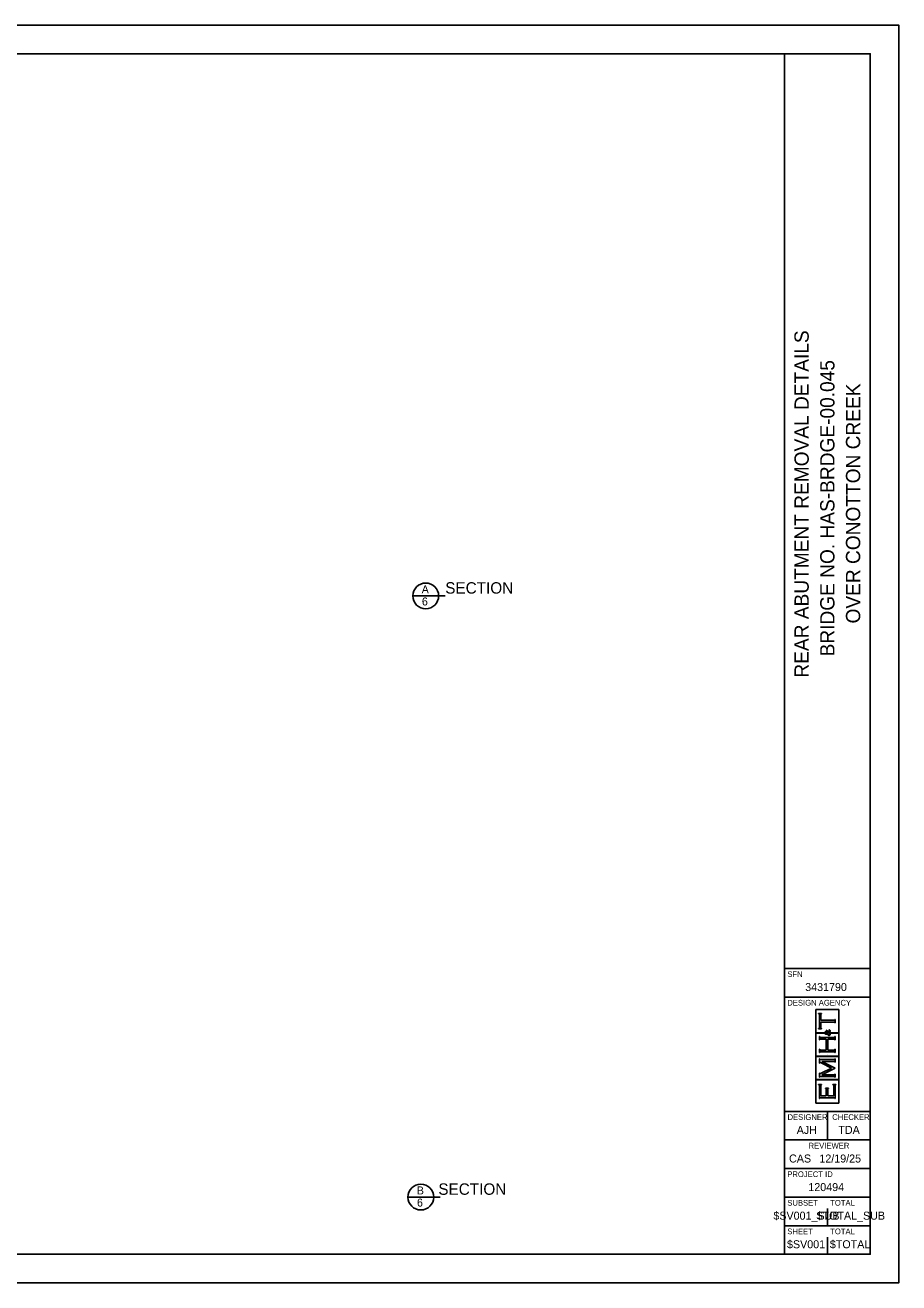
# Model space of a CAD drawing. Extents: x 0 to 34, y 0 to 22.
# Drawn here: x 18.73 to 34, y 0 to 22 of the extents above; entities that cross this region are included whole.
import ezdxf

# ---------------------------------------------------------------- set-up
doc = ezdxf.new("R2010")
doc.units = 0
for name, color, linetype in [('BR_P_Gen_Text', 7, 'Continuous'), ('SH_Border', 7, 'Continuous'), ('SH_Cut_Line', 7, 'Continuous'), ('SH_Data', 7, 'Continuous'), ('SH_Text', 7, 'Continuous')]:
    doc.layers.add(name, color=color, linetype=linetype)

msp = doc.modelspace()

# ---------------------------------------------------------------- linework, layer by layer
at = {"layer": 'SH_Border'}
for p, q in [((32, 0.5), (32, 21.5)), ((32, 5.5), (33.5, 5.5)), ((32, 5), (33.5, 5)), ((32, 3), (33.5, 3)), ((32.75, 3), (32.75, 2.5)), ((32, 2.5), (33.5, 2.5)), ((32, 2), (33.5, 2)), ((32, 1.5), (33.5, 1.5)), ((32, 1), (33.5, 1))]:
    msp.add_line(p, q, dxfattribs=at)
msp.add_lwpolyline([(1.5, 21.5), (33.5, 21.5), (33.5, 0.5), (1.5, 0.5)], close=True, dxfattribs=at)
at = {"layer": 'SH_Cut_Line'}
msp.add_lwpolyline([(0, 0), (34, 0), (34, 22), (0, 22)], close=True, dxfattribs=at)
at = {"layer": 'SH_Data'}
for p, q in [((32.952, 4.779), (32.547, 4.779)), ((32.547, 4.779), (32.547, 4.375)), ((32.598, 4.704), (32.598, 4.711)), ((32.598, 4.711), (32.65, 4.711)), ((32.603, 4.703), (32.598, 4.704)), ((32.606, 4.701), (32.603, 4.703)), ((32.608, 4.699), (32.606, 4.701)), ((32.61, 4.696), (32.608, 4.699)), ((32.611, 4.692), (32.61, 4.696)), ((32.611, 4.687), (32.611, 4.692)), ((32.611, 4.468), (32.611, 4.687)), ((32.638, 4.696), (32.637, 4.692)), ((32.637, 4.692), (32.637, 4.687)), ((32.637, 4.687), (32.637, 4.593)), ((32.64, 4.699), (32.638, 4.696)), ((32.642, 4.701), (32.64, 4.699)), ((32.645, 4.703), (32.642, 4.701)), ((32.65, 4.704), (32.645, 4.703)), ((32.65, 4.711), (32.65, 4.704)), ((32.952, 4.375), (32.952, 4.779)), ((32.598, 4.45), (32.603, 4.451)), ((32.598, 4.444), (32.598, 4.45)), ((32.65, 4.444), (32.598, 4.444)), ((32.603, 4.451), (32.606, 4.453)), ((32.606, 4.453), (32.608, 4.455)), ((32.608, 4.455), (32.61, 4.458)), ((32.61, 4.458), (32.611, 4.462)), ((32.611, 4.462), (32.611, 4.468)), ((32.637, 4.593), (32.864, 4.593)), ((32.864, 4.561), (32.637, 4.561)), ((32.637, 4.561), (32.637, 4.468)), ((32.637, 4.468), (32.637, 4.462)), ((32.637, 4.462), (32.638, 4.458)), ((32.638, 4.458), (32.64, 4.455)), ((32.64, 4.455), (32.642, 4.453)), ((32.642, 4.453), (32.645, 4.451)), ((32.645, 4.451), (32.65, 4.45)), ((32.65, 4.45), (32.65, 4.444)), ((32.738, 4.393), (32.738, 4.422)), ((32.738, 4.422), (32.741, 4.422)), ((32.741, 4.422), (32.741, 4.418)), ((32.741, 4.418), (32.742, 4.415)), ((32.742, 4.415), (32.743, 4.413)), ((32.743, 4.413), (32.745, 4.411)), ((32.745, 4.411), (32.749, 4.408)), ((32.749, 4.408), (32.756, 4.404)), ((32.756, 4.404), (32.763, 4.4)), ((32.763, 4.4), (32.77, 4.396)), ((32.779, 4.423), (32.781, 4.426)), ((32.782, 4.422), (32.779, 4.423)), ((32.781, 4.426), (32.787, 4.424)), ((32.785, 4.421), (32.782, 4.422)), ((32.784, 4.398), (32.786, 4.401)), ((32.786, 4.419), (32.785, 4.421)), ((32.788, 4.417), (32.786, 4.419)), ((32.786, 4.401), (32.788, 4.404)), ((32.787, 4.424), (32.792, 4.421)), ((32.789, 4.414), (32.788, 4.417)), ((32.788, 4.404), (32.789, 4.408)), ((32.789, 4.411), (32.789, 4.414)), ((32.789, 4.408), (32.789, 4.411)), ((32.792, 4.421), (32.795, 4.418)), ((32.795, 4.418), (32.798, 4.414)), ((32.798, 4.414), (32.799, 4.41)), ((32.799, 4.401), (32.798, 4.397)), ((32.799, 4.41), (32.799, 4.405)), ((32.799, 4.405), (32.799, 4.401)), ((32.864, 4.593), (32.869, 4.593)), ((32.87, 4.561), (32.864, 4.561)), ((32.869, 4.593), (32.873, 4.594)), ((32.874, 4.56), (32.87, 4.561)), ((32.873, 4.594), (32.876, 4.596)), ((32.876, 4.559), (32.874, 4.56)), ((32.876, 4.596), (32.878, 4.597)), ((32.878, 4.557), (32.876, 4.559)), ((32.878, 4.597), (32.88, 4.601)), ((32.88, 4.553), (32.878, 4.557)), ((32.88, 4.601), (32.881, 4.606)), ((32.881, 4.548), (32.88, 4.553)), ((32.881, 4.606), (32.888, 4.606)), ((32.888, 4.548), (32.881, 4.548)), ((32.888, 4.606), (32.888, 4.548)), ((32.547, 4.375), (32.696, 4.375)), ((32.696, 4.369), (32.547, 4.369)), ((32.547, 4.369), (32.547, 3.965)), ((32.611, 4.249), (32.611, 4.307)), ((32.611, 4.307), (32.617, 4.307)), ((32.617, 4.249), (32.611, 4.249)), ((32.617, 4.307), (32.619, 4.302)), ((32.618, 4.254), (32.617, 4.249)), ((32.62, 4.258), (32.618, 4.254)), ((32.619, 4.302), (32.62, 4.298)), ((32.62, 4.298), (32.623, 4.297)), ((32.623, 4.26), (32.62, 4.258)), ((32.623, 4.297), (32.625, 4.295)), ((32.625, 4.261), (32.623, 4.26)), ((32.625, 4.295), (32.629, 4.294)), ((32.629, 4.262), (32.625, 4.261)), ((32.629, 4.294), (32.635, 4.294)), ((32.635, 4.262), (32.629, 4.262)), ((32.635, 4.294), (32.864, 4.294)), ((32.732, 4.262), (32.635, 4.262)), ((32.696, 4.375), (32.696, 4.369)), ((32.703, 4.379), (32.705, 4.383)), ((32.703, 4.373), (32.703, 4.379)), ((32.703, 4.368), (32.703, 4.373)), ((32.705, 4.363), (32.703, 4.368)), ((32.705, 4.383), (32.708, 4.387)), ((32.708, 4.358), (32.705, 4.363)), ((32.708, 4.387), (32.711, 4.39)), ((32.709, 4.379), (32.708, 4.376)), ((32.708, 4.376), (32.708, 4.373)), ((32.708, 4.373), (32.708, 4.369)), ((32.708, 4.369), (32.71, 4.366)), ((32.712, 4.353), (32.708, 4.358)), ((32.712, 4.381), (32.709, 4.379)), ((32.71, 4.366), (32.712, 4.364)), ((32.711, 4.39), (32.715, 4.392)), ((32.714, 4.383), (32.712, 4.381)), ((32.712, 4.364), (32.715, 4.362)), ((32.718, 4.35), (32.712, 4.353)), ((32.716, 4.384), (32.714, 4.383)), ((32.715, 4.392), (32.72, 4.392)), ((32.715, 4.362), (32.718, 4.361)), ((32.72, 4.384), (32.716, 4.384)), ((32.718, 4.361), (32.721, 4.361)), ((32.726, 4.35), (32.718, 4.35)), ((32.72, 4.392), (32.725, 4.392)), ((32.724, 4.384), (32.72, 4.384)), ((32.721, 4.361), (32.723, 4.361)), ((32.723, 4.361), (32.725, 4.362)), ((32.728, 4.382), (32.724, 4.384)), ((32.725, 4.392), (32.729, 4.39)), ((32.725, 4.362), (32.728, 4.362)), ((32.729, 4.35), (32.726, 4.35)), ((32.731, 4.38), (32.728, 4.382)), ((32.728, 4.362), (32.731, 4.363)), ((32.729, 4.39), (32.732, 4.387)), ((32.731, 4.35), (32.729, 4.35)), ((32.734, 4.377), (32.731, 4.38)), ((32.731, 4.363), (32.735, 4.365)), ((32.734, 4.351), (32.731, 4.35)), ((32.732, 4.387), (32.736, 4.383)), ((32.732, 4.072), (32.732, 4.262)), ((32.737, 4.372), (32.734, 4.377)), ((32.737, 4.352), (32.734, 4.351)), ((32.735, 4.365), (32.74, 4.367)), ((32.736, 4.383), (32.74, 4.378)), ((32.74, 4.367), (32.737, 4.372)), ((32.741, 4.353), (32.737, 4.352)), ((32.741, 4.393), (32.738, 4.393)), ((32.74, 4.378), (32.744, 4.369)), ((32.742, 4.396), (32.741, 4.395)), ((32.741, 4.395), (32.741, 4.393)), ((32.746, 4.355), (32.741, 4.353)), ((32.743, 4.397), (32.742, 4.396)), ((32.745, 4.399), (32.743, 4.397)), ((32.744, 4.369), (32.754, 4.375)), ((32.746, 4.399), (32.745, 4.399)), ((32.748, 4.399), (32.746, 4.399)), ((32.752, 4.344), (32.746, 4.355)), ((32.755, 4.399), (32.748, 4.399)), ((32.756, 4.36), (32.751, 4.357)), ((32.751, 4.357), (32.754, 4.352)), ((32.757, 4.337), (32.752, 4.344)), ((32.754, 4.375), (32.764, 4.381)), ((32.754, 4.352), (32.757, 4.348)), ((32.763, 4.395), (32.755, 4.399)), ((32.761, 4.363), (32.756, 4.36)), ((32.757, 4.348), (32.761, 4.345)), ((32.763, 4.333), (32.757, 4.337)), ((32.864, 4.262), (32.759, 4.262)), ((32.759, 4.262), (32.759, 4.072)), ((32.764, 4.365), (32.761, 4.363)), ((32.761, 4.345), (32.765, 4.343)), ((32.772, 4.387), (32.763, 4.395)), ((32.768, 4.329), (32.763, 4.333)), ((32.764, 4.381), (32.772, 4.387)), ((32.768, 4.367), (32.764, 4.365)), ((32.765, 4.343), (32.769, 4.341)), ((32.774, 4.372), (32.768, 4.367)), ((32.774, 4.327), (32.768, 4.329)), ((32.769, 4.341), (32.773, 4.341)), ((32.77, 4.396), (32.776, 4.391)), ((32.773, 4.341), (32.778, 4.341)), ((32.782, 4.378), (32.774, 4.372)), ((32.779, 4.327), (32.774, 4.327)), ((32.776, 4.391), (32.781, 4.395)), ((32.778, 4.341), (32.782, 4.343)), ((32.785, 4.327), (32.779, 4.327)), ((32.781, 4.395), (32.784, 4.398)), ((32.786, 4.373), (32.782, 4.378)), ((32.782, 4.343), (32.786, 4.346)), ((32.79, 4.329), (32.785, 4.327)), ((32.791, 4.386), (32.786, 4.381)), ((32.786, 4.381), (32.791, 4.376)), ((32.788, 4.369), (32.786, 4.373)), ((32.786, 4.346), (32.789, 4.349)), ((32.79, 4.367), (32.788, 4.369)), ((32.789, 4.349), (32.791, 4.353)), ((32.791, 4.364), (32.79, 4.367)), ((32.793, 4.334), (32.79, 4.329)), ((32.794, 4.39), (32.791, 4.386)), ((32.791, 4.376), (32.795, 4.37)), ((32.791, 4.361), (32.791, 4.364)), ((32.791, 4.359), (32.791, 4.361)), ((32.791, 4.353), (32.791, 4.359)), ((32.797, 4.338), (32.793, 4.334)), ((32.796, 4.394), (32.794, 4.39)), ((32.795, 4.37), (32.797, 4.366)), ((32.798, 4.397), (32.796, 4.394)), ((32.797, 4.366), (32.798, 4.361)), ((32.799, 4.344), (32.797, 4.338)), ((32.798, 4.361), (32.799, 4.357)), ((32.803, 4.369), (32.799, 4.375)), ((32.799, 4.375), (32.952, 4.375)), ((32.799, 4.357), (32.799, 4.352)), ((32.799, 4.352), (32.799, 4.344)), ((32.952, 4.369), (32.803, 4.369)), ((32.864, 4.294), (32.869, 4.294)), ((32.87, 4.262), (32.864, 4.262)), ((32.869, 4.294), (32.873, 4.295)), ((32.874, 4.261), (32.87, 4.262)), ((32.873, 4.295), (32.876, 4.297)), ((32.876, 4.26), (32.874, 4.261)), ((32.876, 4.297), (32.878, 4.298)), ((32.878, 4.258), (32.876, 4.26)), ((32.878, 4.298), (32.88, 4.302)), ((32.88, 4.254), (32.878, 4.258)), ((32.88, 4.302), (32.881, 4.307)), ((32.881, 4.249), (32.88, 4.254)), ((32.881, 4.307), (32.888, 4.307)), ((32.888, 4.249), (32.881, 4.249)), ((32.888, 4.307), (32.888, 4.249)), ((32.952, 3.965), (32.952, 4.369)), ((32.547, 3.965), (32.952, 3.965)), ((32.611, 4.027), (32.611, 4.085)), ((32.611, 4.085), (32.617, 4.085)), ((32.617, 4.027), (32.611, 4.027)), ((32.617, 4.085), (32.619, 4.08)), ((32.618, 4.032), (32.617, 4.027)), ((32.62, 4.036), (32.618, 4.032)), ((32.619, 4.08), (32.62, 4.076)), ((32.62, 4.076), (32.623, 4.074)), ((32.623, 4.037), (32.62, 4.036)), ((32.623, 4.074), (32.625, 4.073)), ((32.625, 4.039), (32.623, 4.037)), ((32.625, 4.073), (32.629, 4.072)), ((32.629, 4.04), (32.625, 4.039)), ((32.629, 4.072), (32.635, 4.072)), ((32.635, 4.04), (32.629, 4.04)), ((32.635, 4.072), (32.732, 4.072)), ((32.864, 4.04), (32.635, 4.04)), ((32.75, 4), (32.75, 4)), ((32.759, 4.072), (32.864, 4.072)), ((32.864, 4.072), (32.87, 4.072)), ((32.87, 4.04), (32.864, 4.04)), ((32.87, 4.072), (32.874, 4.073)), ((32.874, 4.039), (32.87, 4.04)), ((32.874, 4.073), (32.876, 4.074)), ((32.876, 4.038), (32.874, 4.039)), ((32.876, 4.074), (32.878, 4.076)), ((32.878, 4.036), (32.876, 4.038)), ((32.878, 4.076), (32.88, 4.08)), ((32.88, 4.032), (32.878, 4.036)), ((32.88, 4.08), (32.881, 4.085)), ((32.881, 4.027), (32.88, 4.032)), ((32.881, 4.085), (32.888, 4.085)), ((32.888, 4.027), (32.881, 4.027)), ((32.888, 4.085), (32.888, 4.027)), ((32.952, 3.959), (32.547, 3.959)), ((32.547, 3.959), (32.547, 3.555)), ((32.611, 3.845), (32.611, 3.918)), ((32.611, 3.918), (32.617, 3.918)), ((32.617, 3.845), (32.611, 3.845)), ((32.617, 3.918), (32.619, 3.912)), ((32.62, 3.852), (32.617, 3.845)), ((32.619, 3.912), (32.62, 3.909)), ((32.62, 3.909), (32.623, 3.907)), ((32.622, 3.855), (32.62, 3.852)), ((32.626, 3.855), (32.622, 3.855)), ((32.623, 3.907), (32.625, 3.905)), ((32.625, 3.905), (32.629, 3.905)), ((32.629, 3.855), (32.626, 3.855)), ((32.629, 3.905), (32.635, 3.905)), ((32.633, 3.853), (32.629, 3.855)), ((32.64, 3.85), (32.633, 3.853)), ((32.635, 3.905), (32.864, 3.905)), ((32.825, 3.757), (32.64, 3.85)), ((32.641, 3.665), (32.825, 3.757)), ((32.864, 3.873), (32.654, 3.873)), ((32.654, 3.873), (32.888, 3.755)), ((32.888, 3.755), (32.654, 3.638)), ((32.864, 3.905), (32.869, 3.905)), ((32.87, 3.873), (32.864, 3.873)), ((32.869, 3.905), (32.873, 3.905)), ((32.874, 3.872), (32.87, 3.873)), ((32.873, 3.905), (32.876, 3.907)), ((32.876, 3.87), (32.874, 3.872)), ((32.876, 3.907), (32.878, 3.909)), ((32.878, 3.869), (32.876, 3.87)), ((32.878, 3.909), (32.88, 3.912)), ((32.88, 3.865), (32.878, 3.869)), ((32.88, 3.912), (32.881, 3.918)), ((32.881, 3.86), (32.88, 3.865)), ((32.881, 3.918), (32.888, 3.918)), ((32.888, 3.86), (32.881, 3.86)), ((32.888, 3.918), (32.888, 3.86)), ((32.952, 3.555), (32.952, 3.959)), ((32.547, 3.555), (32.952, 3.555)), ((32.952, 3.549), (32.547, 3.549)), ((32.547, 3.549), (32.547, 3.145)), ((32.611, 3.596), (32.611, 3.668)), ((32.611, 3.668), (32.617, 3.668)), ((32.617, 3.596), (32.611, 3.596)), ((32.617, 3.668), (32.62, 3.662)), ((32.618, 3.602), (32.617, 3.596)), ((32.62, 3.605), (32.618, 3.602)), ((32.62, 3.662), (32.622, 3.658)), ((32.623, 3.607), (32.62, 3.605)), ((32.622, 3.658), (32.626, 3.658)), ((32.625, 3.609), (32.623, 3.607)), ((32.629, 3.609), (32.625, 3.609)), ((32.626, 3.658), (32.627, 3.658)), ((32.627, 3.658), (32.633, 3.661)), ((32.635, 3.609), (32.629, 3.609)), ((32.633, 3.661), (32.641, 3.665)), ((32.864, 3.609), (32.635, 3.609)), ((32.654, 3.638), (32.864, 3.638)), ((32.864, 3.638), (32.869, 3.638)), ((32.87, 3.609), (32.864, 3.609)), ((32.869, 3.638), (32.873, 3.639)), ((32.874, 3.609), (32.87, 3.609)), ((32.873, 3.639), (32.876, 3.641)), ((32.876, 3.607), (32.874, 3.609)), ((32.876, 3.641), (32.878, 3.643)), ((32.878, 3.605), (32.876, 3.607)), ((32.878, 3.643), (32.88, 3.646)), ((32.88, 3.602), (32.878, 3.605)), ((32.88, 3.646), (32.881, 3.651)), ((32.881, 3.596), (32.88, 3.602)), ((32.881, 3.651), (32.888, 3.651)), ((32.888, 3.596), (32.881, 3.596)), ((32.888, 3.651), (32.888, 3.596)), ((32.952, 3.145), (32.952, 3.549)), ((32.598, 3.462), (32.598, 3.469)), ((32.598, 3.469), (32.65, 3.469)), ((32.603, 3.461), (32.598, 3.462)), ((32.606, 3.459), (32.603, 3.461)), ((32.608, 3.457), (32.606, 3.459)), ((32.61, 3.455), (32.608, 3.457)), ((32.611, 3.451), (32.61, 3.455)), ((32.611, 3.445), (32.611, 3.451)), ((32.611, 3.225), (32.611, 3.445)), ((32.64, 3.457), (32.638, 3.455)), ((32.638, 3.455), (32.638, 3.451)), ((32.638, 3.451), (32.638, 3.445)), ((32.638, 3.445), (32.638, 3.27)), ((32.642, 3.459), (32.64, 3.457)), ((32.645, 3.461), (32.642, 3.459)), ((32.65, 3.462), (32.645, 3.461)), ((32.65, 3.469), (32.65, 3.462)), ((32.719, 3.402), (32.719, 3.408)), ((32.719, 3.408), (32.772, 3.408)), ((32.724, 3.401), (32.719, 3.402)), ((32.728, 3.399), (32.724, 3.401)), ((32.729, 3.396), (32.728, 3.399)), ((32.731, 3.394), (32.729, 3.396)), ((32.732, 3.39), (32.731, 3.394)), ((32.732, 3.384), (32.732, 3.39)), ((32.732, 3.27), (32.732, 3.384)), ((32.76, 3.394), (32.759, 3.39)), ((32.759, 3.39), (32.759, 3.384)), ((32.759, 3.384), (32.759, 3.27)), ((32.761, 3.396), (32.76, 3.394)), ((32.763, 3.399), (32.761, 3.396)), ((32.767, 3.401), (32.763, 3.399)), ((32.772, 3.402), (32.767, 3.401)), ((32.772, 3.408), (32.772, 3.402)), ((32.848, 3.465), (32.848, 3.472)), ((32.848, 3.472), (32.901, 3.472)), ((32.853, 3.464), (32.848, 3.465)), ((32.857, 3.462), (32.853, 3.464)), ((32.859, 3.46), (32.857, 3.462)), ((32.86, 3.458), (32.859, 3.46)), ((32.861, 3.453), (32.86, 3.458)), ((32.861, 3.448), (32.861, 3.453)), ((32.861, 3.27), (32.861, 3.448)), ((32.889, 3.457), (32.888, 3.453)), ((32.888, 3.453), (32.888, 3.448)), ((32.888, 3.448), (32.888, 3.225)), ((32.891, 3.46), (32.889, 3.457)), ((32.892, 3.462), (32.891, 3.46)), ((32.896, 3.464), (32.892, 3.462)), ((32.901, 3.465), (32.896, 3.464)), ((32.901, 3.472), (32.901, 3.465)), ((32.547, 3.145), (32.952, 3.145)), ((32.617, 3.225), (32.611, 3.225)), ((32.619, 3.23), (32.617, 3.225)), ((32.62, 3.234), (32.619, 3.23)), ((32.623, 3.235), (32.62, 3.234)), ((32.625, 3.237), (32.623, 3.235)), ((32.629, 3.238), (32.625, 3.237)), ((32.635, 3.238), (32.629, 3.238)), ((32.864, 3.238), (32.635, 3.238)), ((32.638, 3.27), (32.732, 3.27)), ((32.759, 3.27), (32.861, 3.27)), ((32.87, 3.238), (32.864, 3.238)), ((32.874, 3.237), (32.87, 3.238)), ((32.876, 3.235), (32.874, 3.237)), ((32.878, 3.234), (32.876, 3.235)), ((32.88, 3.23), (32.878, 3.234)), ((32.881, 3.225), (32.88, 3.23)), ((32.888, 3.225), (32.881, 3.225)), ((32.75, 1), (32.75, 1.3)), ((32.375, 0.675), (32.375, 0.675)), ((32.75, 0.5), (32.75, 0.8))]:
    msp.add_line(p, q, dxfattribs=at)
at = {"layer": 'SH_Text'}
for p, q in [((25.505, 12.016), (26.07, 12.016)), ((25.418, 1.5), (25.984, 1.5))]:
    msp.add_line(p, q, dxfattribs=at)
for centre in [(25.729, 12.016), (25.643, 1.5)]:
    msp.add_circle(centre, 0.225, dxfattribs=at)

# ---------------------------------------------------------------- texts
at = {"layer": 'BR_P_Gen_Text'}
for p in [(26.07, 12.056), (25.949, 1.54)]:
    msp.add_text('SECTION', height=0.2, dxfattribs=at).set_placement(p)
at = {"layer": 'SH_Data'}
for s, p in [('REAR ABUTMENT REMOVAL DETAILS', (32.425, 10.587)), ('BRIDGE NO. HAS-BRDGE-00.045', (32.875, 10.958)), ('OVER CONOTTON CREEK', (33.325, 11.534))]:
    msp.add_text(s, height=0.25, rotation=90, dxfattribs=at).set_placement(p)
for s, height, p in [('SFN', 0.1, (32.05, 5.35)), ('3431790', 0.14, (32.363, 5.105)), ('DESIGN AGENCY', 0.1, (32.05, 4.85)), ('DESIGNER', 0.1, (32.054, 2.85)), ('CHECKER', 0.1, (32.835, 2.85)), ('AJH', 0.14, (32.215, 2.605)), ('TDA', 0.14, (32.943, 2.605)), ('REVIEWER', 0.1, (32.422, 2.35)), ('CAS', 0.14, (32.081, 2.105)), ('12/19/25', 0.14, (32.611, 2.105)), ('PROJECT ID', 0.1, (32.05, 1.85)), ('120494', 0.14, (32.418, 1.605)), ('SUBSET', 0.1, (32.05, 1.35)), ('TOTAL', 0.1, (32.8, 1.35)), ('$SV001_SUB', 0.14, (31.807, 1.105)), ('$TOTAL_SUB', 0.14, (32.562, 1.105)), ('SHEET', 0.1, (32.05, 0.85)), ('TOTAL', 0.1, (32.8, 0.85)), ('$SV001', 0.14, (32.045, 0.605)), ('$TOTAL', 0.14, (32.794, 0.605))]:
    msp.add_text(s, height=height, dxfattribs=at).set_placement(p)
at = {"layer": 'SH_Text'}
for s, p in [('A', (25.658, 12.061)), ('6', (25.662, 11.849)), ('B', (25.572, 1.546)), ('6', (25.576, 1.334))]:
    msp.add_text(s, height=0.14, dxfattribs=at).set_placement(p)

doc.saveas('drawing.dxf')
